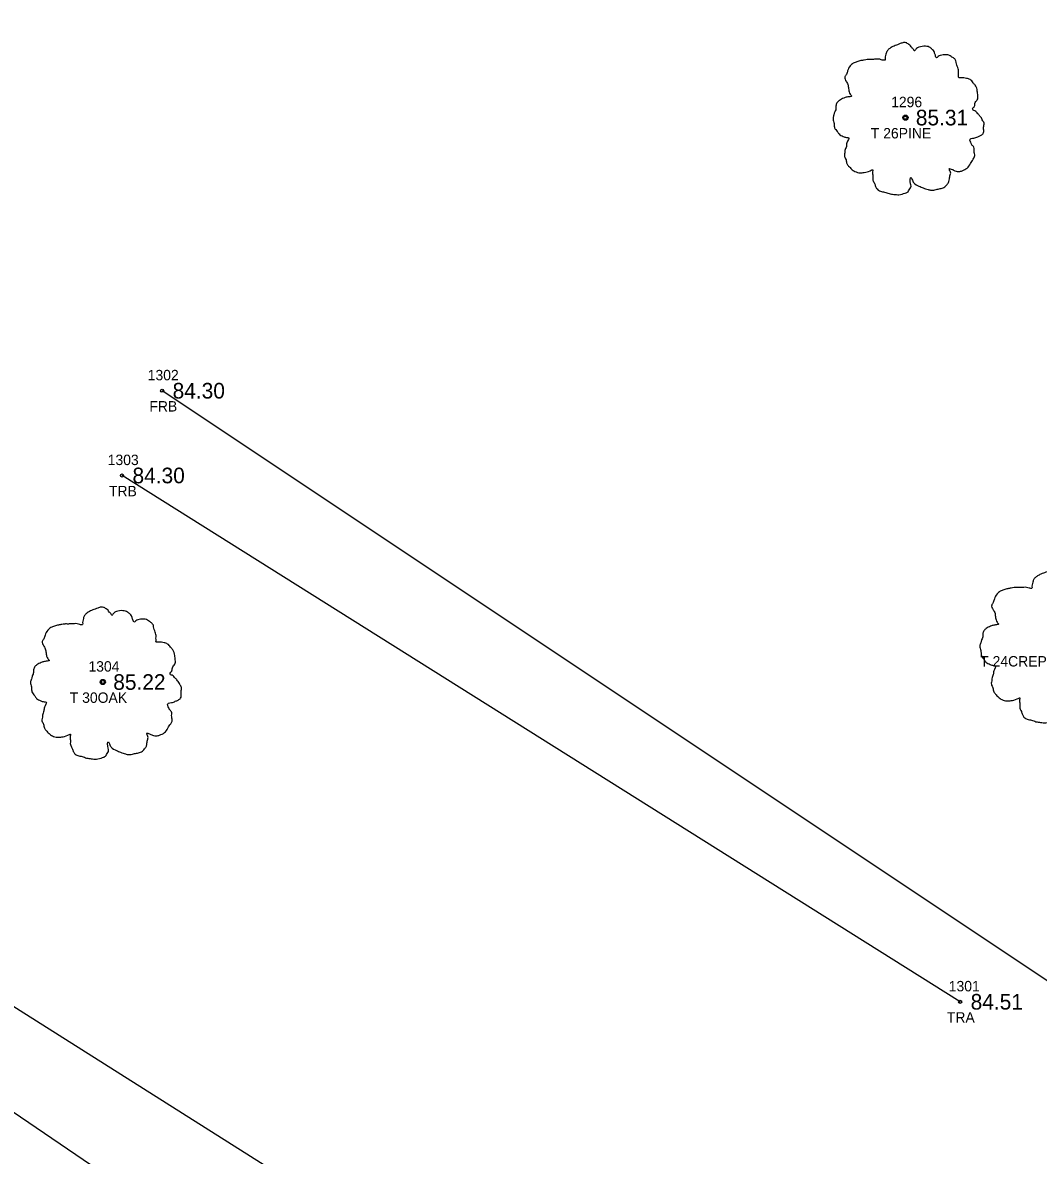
# Model space of a CAD drawing. Extents: x 2139392 to 2143384, y 505395 to 510520.
# Drawn here: x 2141084.9 to 2141182.4, y 509825.4 to 509934.1 of the extents above; entities that cross this region are included whole.
import ezdxf

# ---------------------------------------------------------------- set-up
doc = ezdxf.new("R2010")
doc.units = 0
for name, color, linetype in [('RD_EX_Driveway', 7, 'Continuous'), ('RD_EX_Fence_Other', 7, 'Continuous'), ('RD_EX_Fence_Other_txCode', 7, 'Continuous'), ('RD_EX_TX_Fence_Other_ELEV', 7, 'Continuous'), ('RD_EX_TX_VEG_ELEV', 7, 'Continuous'), ('RD_EX_VEG', 7, 'Continuous'), ('RD_EX_VEG_txCode', 7, 'Continuous'), ('RD_SMD_Locator', 7, 'Continuous')]:
    doc.layers.add(name, color=color, linetype=linetype)

msp = doc.modelspace()

# ---------------------------------------------------------------- linework, layer by layer
at = {"layer": 'RD_EX_Driveway'}
for p, q in [((2141078.27, 509843.32), (2141182.34, 509777.58)), ((2141073.6, 509836.63), (2141177.46, 509766.07))]:
    msp.add_line(p, q, dxfattribs=at)
at = {"layer": 'RD_EX_Fence_Other'}
msp.add_lwpolyline([(2141253.77, 509976.78), (2141199.74, 509831.14), (2141098.33, 509898.78)], dxfattribs=at)
at = {"layer": 'RD_EX_VEG'}
msp.add_line((2141174.93, 509840.11), (2141094.48, 509890.64), dxfattribs=at)
for centre, radius in [((2141169.67, 509925), 0.25), ((2141169.65, 509924.99), 0.0001), ((2141092.63, 509870.81), 0.25), ((2141092.62, 509870.79), 0.0001)]:
    msp.add_circle(centre, radius, dxfattribs=at)
for points in [[(2141169.8, 509932.17), (2141169.5, 509932.2), (2141169.17, 509932.1), (2141168.92, 509932), (2141168.7, 509931.92), (2141168.47, 509931.82), (2141168.17, 509931.65), (2141167.95, 509931.45), (2141167.82, 509931.2), (2141167.77, 509930.97), (2141167.72, 509930.7), (2141167.72, 509930.52), (2141167.6, 509930.5), (2141167.45, 509930.52), (2141167.2, 509930.6), (2141166.95, 509930.6), (2141166.7, 509930.6), (2141166.35, 509930.57), (2141166, 509930.57), (2141165.72, 509930.52), (2141165.4, 509930.47), (2141165.02, 509930.35), (2141164.67, 509930.22), (2141164.37, 509929.97), (2141164.12, 509929.5), (2141164, 509929.15), (2141163.85, 509928.9), (2141164, 509928.45), (2141164.17, 509928.1), (2141164.2, 509927.9), (2141164.27, 509927.47), (2141164.37, 509927.25), (2141164.5, 509927.05), (2141164.42, 509927.02), (2141164.05, 509926.97), (2141163.75, 509926.87), (2141163.33, 509926.65), (2141163.1, 509926.42), (2141163, 509926.1), (2141162.98, 509925.75), (2141162.88, 509925.55), (2141162.8, 509925.28), (2141162.78, 509925.2), (2141162.73, 509924.88), (2141162.83, 509924.43), (2141162.85, 509924.08), (2141162.98, 509923.85), (2141163.13, 509923.68), (2141163.3, 509923.43), (2141163.7, 509923.2), (2141164.02, 509923.1), (2141164.22, 509923.08), (2141164.05, 509922.58), (2141164, 509922.23), (2141163.87, 509921.83), (2141163.87, 509921.75), (2141163.82, 509921.28), (2141163.97, 509920.95), (2141164.05, 509920.58), (2141164.22, 509920.35), (2141164.5, 509920.05), (2141164.82, 509919.83), (2141165.32, 509919.7), (2141165.72, 509919.73), (2141166.3, 509919.9), (2141166.55, 509919.98), (2141166.52, 509919.8), (2141166.55, 509919.43), (2141166.55, 509919), (2141166.7, 509918.68), (2141166.8, 509918.4), (2141166.95, 509918.15), (2141167.27, 509917.93), (2141167.67, 509917.85), (2141168.1, 509917.7), (2141168.55, 509917.63), (2141169.05, 509917.6), (2141169.65, 509917.75), (2141169.92, 509917.88), (2141170.02, 509918.05), (2141170.22, 509918.43), (2141170.17, 509918.65), (2141170.2, 509919.25), (2141170.3, 509919.08), (2141170.47, 509918.73), (2141170.97, 509918.43), (2141171.37, 509918.25), (2141171.85, 509918.1), (2141172.15, 509918.03), (2141172.62, 509918.1), (2141173, 509918.18), (2141173.37, 509918.3), (2141173.67, 509918.58), (2141173.85, 509918.85), (2141173.9, 509919.13), (2141173.97, 509919.5), (2141174.02, 509919.68)], [(2141174.02, 509919.68), (2141173.95, 509919.85), (2141173.9, 509920.1), (2141173.97, 509920.08), (2141174.15, 509920.03), (2141174.42, 509919.9), (2141174.65, 509919.83), (2141174.97, 509919.85), (2141175.24, 509919.95), (2141175.69, 509920.23), (2141175.97, 509920.7), (2141176.24, 509921.1), (2141176.32, 509921.43), (2141176.27, 509921.65), (2141176.24, 509922.15), (2141176.04, 509922.4), (2141175.99, 509922.53), (2141175.89, 509922.93), (2141175.97, 509922.98), (2141176.24, 509923.03), (2141176.62, 509923.15), (2141176.89, 509923.28), (2141177.12, 509923.45), (2141177.19, 509923.68), (2141177.17, 509924.08), (2141177.22, 509924.48), (2141177.14, 509924.63), (2141177.04, 509924.78), (2141176.97, 509924.98), (2141176.82, 509925.13), (2141176.72, 509925.28), (2141176.62, 509925.37), (2141176.49, 509925.52), (2141176.32, 509925.65), (2141176.17, 509925.7), (2141176.12, 509925.85), (2141176.27, 509926.05), (2141176.32, 509926.15), (2141176.34, 509926.37), (2141176.57, 509926.72), (2141176.62, 509927.12), (2141176.57, 509927.55), (2141176.52, 509927.82), (2141176.37, 509928.1), (2141176.17, 509928.35), (2141176.04, 509928.52), (2141175.87, 509928.65), (2141175.54, 509928.77), (2141175.29, 509928.82), (2141174.94, 509928.82), (2141174.75, 509928.87), (2141174.77, 509928.92), (2141174.77, 509929.07), (2141174.77, 509929.35), (2141174.7, 509929.8), (2141174.55, 509930.3), (2141174.55, 509930.32), (2141174.45, 509930.57), (2141174.22, 509930.77), (2141174.05, 509930.87), (2141173.85, 509931), (2141173.6, 509931.02), (2141173.3, 509931.02), (2141173.02, 509930.97), (2141172.82, 509930.87), (2141172.65, 509930.75), (2141172.57, 509930.9), (2141172.47, 509931.2), (2141172.42, 509931.35), (2141172.27, 509931.52), (2141172.05, 509931.72), (2141171.6, 509931.85), (2141170.97, 509931.77), (2141170.67, 509931.57), (2141170.52, 509931.4), (2141170.47, 509931.52), (2141170.27, 509931.72), (2141170.17, 509931.9), (2141170, 509932.02), (2141169.85, 509932.12), (2141169.75, 509932.17)], [(2141183.9, 509881.47), (2141183.6, 509881.5), (2141183.27, 509881.4), (2141183.02, 509881.3), (2141182.8, 509881.22), (2141182.57, 509881.12), (2141182.27, 509880.95), (2141182.05, 509880.75), (2141181.92, 509880.5), (2141181.87, 509880.27), (2141181.82, 509880), (2141181.82, 509879.82), (2141181.7, 509879.8), (2141181.55, 509879.82), (2141181.3, 509879.9), (2141181.05, 509879.9), (2141180.8, 509879.9), (2141180.45, 509879.87), (2141180.1, 509879.87), (2141179.82, 509879.82), (2141179.5, 509879.77), (2141179.12, 509879.65), (2141178.77, 509879.52), (2141178.47, 509879.27), (2141178.22, 509878.8), (2141178.1, 509878.45), (2141177.95, 509878.2), (2141178.1, 509877.75), (2141178.27, 509877.4), (2141178.3, 509877.2), (2141178.37, 509876.77), (2141178.47, 509876.55), (2141178.6, 509876.35), (2141178.52, 509876.32), (2141178.15, 509876.27), (2141177.85, 509876.17), (2141177.42, 509875.95), (2141177.2, 509875.72), (2141177.1, 509875.4), (2141177.07, 509875.05), (2141176.97, 509874.85), (2141176.9, 509874.57), (2141176.87, 509874.5), (2141176.82, 509874.17), (2141176.92, 509873.72), (2141176.95, 509873.37), (2141177.07, 509873.15), (2141177.22, 509872.97), (2141177.4, 509872.72), (2141177.8, 509872.5), (2141178.12, 509872.4), (2141178.32, 509872.37), (2141178.15, 509871.87), (2141178.1, 509871.53), (2141177.97, 509871.13), (2141177.97, 509871.05), (2141177.92, 509870.58), (2141178.07, 509870.25), (2141178.15, 509869.88), (2141178.32, 509869.65), (2141178.6, 509869.35), (2141178.92, 509869.13), (2141179.42, 509869), (2141179.82, 509869.03), (2141180.4, 509869.2), (2141180.65, 509869.28), (2141180.62, 509869.1), (2141180.65, 509868.73), (2141180.65, 509868.3), (2141180.8, 509867.98), (2141180.9, 509867.7), (2141181.05, 509867.45), (2141181.37, 509867.23), (2141181.77, 509867.15), (2141182.2, 509867), (2141182.65, 509866.93), (2141183.15, 509866.9), (2141183.75, 509867.05), (2141184.02, 509867.18), (2141184.12, 509867.35), (2141184.32, 509867.73), (2141184.27, 509867.95), (2141184.3, 509868.55), (2141184.4, 509868.38), (2141184.57, 509868.03), (2141185.07, 509867.73), (2141185.47, 509867.55), (2141185.95, 509867.4), (2141186.25, 509867.33), (2141186.72, 509867.4), (2141187.1, 509867.48), (2141187.47, 509867.6), (2141187.77, 509867.88), (2141187.94, 509868.15), (2141187.99, 509868.43), (2141188.07, 509868.8), (2141188.12, 509868.98)], [(2141092.76, 509877.98), (2141092.46, 509878), (2141092.14, 509877.9), (2141091.89, 509877.81), (2141091.67, 509877.73), (2141091.44, 509877.63), (2141091.14, 509877.46), (2141090.92, 509877.26), (2141090.79, 509877.01), (2141090.74, 509876.78), (2141090.69, 509876.51), (2141090.69, 509876.33), (2141090.57, 509876.31), (2141090.42, 509876.33), (2141090.17, 509876.41), (2141089.92, 509876.41), (2141089.67, 509876.41), (2141089.32, 509876.38), (2141088.97, 509876.38), (2141088.69, 509876.33), (2141088.37, 509876.28), (2141087.99, 509876.16), (2141087.64, 509876.03), (2141087.34, 509875.78), (2141087.09, 509875.31), (2141086.97, 509874.96), (2141086.82, 509874.71), (2141086.97, 509874.26), (2141087.14, 509873.91), (2141087.17, 509873.71), (2141087.24, 509873.28), (2141087.34, 509873.06), (2141087.47, 509872.86), (2141087.39, 509872.83), (2141087.02, 509872.78), (2141086.72, 509872.68), (2141086.29, 509872.46), (2141086.07, 509872.23), (2141085.97, 509871.91), (2141085.94, 509871.56), (2141085.84, 509871.36), (2141085.77, 509871.08), (2141085.74, 509871.01), (2141085.69, 509870.68), (2141085.79, 509870.23), (2141085.82, 509869.88), (2141085.94, 509869.66), (2141086.09, 509869.48), (2141086.27, 509869.23), (2141086.67, 509869.01), (2141086.99, 509868.91), (2141087.19, 509868.88), (2141087.02, 509868.38), (2141086.97, 509868.03), (2141086.84, 509867.63), (2141086.84, 509867.56), (2141086.79, 509867.08), (2141086.94, 509866.76), (2141087.02, 509866.39), (2141087.19, 509866.16), (2141087.47, 509865.86), (2141087.79, 509865.64), (2141088.29, 509865.51), (2141088.69, 509865.54), (2141089.27, 509865.71), (2141089.52, 509865.79), (2141089.49, 509865.61), (2141089.52, 509865.24), (2141089.52, 509864.81), (2141089.67, 509864.49), (2141089.77, 509864.21), (2141089.92, 509863.96), (2141090.24, 509863.74), (2141090.64, 509863.66), (2141091.07, 509863.51), (2141091.52, 509863.44), (2141092.02, 509863.41), (2141092.61, 509863.56), (2141092.89, 509863.69), (2141092.99, 509863.86), (2141093.19, 509864.24), (2141093.14, 509864.46), (2141093.16, 509865.06), (2141093.26, 509864.89), (2141093.44, 509864.54), (2141093.94, 509864.24), (2141094.34, 509864.06), (2141094.81, 509863.91), (2141095.11, 509863.84), (2141095.59, 509863.91), (2141095.96, 509863.99), (2141096.34, 509864.11), (2141096.64, 509864.39), (2141096.81, 509864.66), (2141096.86, 509864.94), (2141096.94, 509865.31), (2141096.99, 509865.49)], [(2141096.99, 509865.49), (2141096.91, 509865.66), (2141096.86, 509865.91), (2141096.94, 509865.89), (2141097.11, 509865.84), (2141097.39, 509865.71), (2141097.61, 509865.64), (2141097.94, 509865.66), (2141098.21, 509865.76), (2141098.66, 509866.04), (2141098.94, 509866.51), (2141099.21, 509866.91), (2141099.29, 509867.23), (2141099.24, 509867.46), (2141099.21, 509867.96), (2141099.01, 509868.21), (2141098.96, 509868.33), (2141098.86, 509868.73), (2141098.94, 509868.78), (2141099.21, 509868.83), (2141099.59, 509868.96), (2141099.86, 509869.08), (2141100.09, 509869.26), (2141100.16, 509869.48), (2141100.14, 509869.88), (2141100.19, 509870.28), (2141100.11, 509870.43), (2141100.01, 509870.58), (2141099.94, 509870.78), (2141099.79, 509870.93), (2141099.69, 509871.08), (2141099.59, 509871.18), (2141099.46, 509871.33), (2141099.29, 509871.46), (2141099.14, 509871.51), (2141099.09, 509871.66), (2141099.24, 509871.86), (2141099.29, 509871.96), (2141099.31, 509872.18), (2141099.54, 509872.53), (2141099.59, 509872.93), (2141099.54, 509873.36), (2141099.49, 509873.63), (2141099.34, 509873.91), (2141099.14, 509874.16), (2141099.01, 509874.33), (2141098.84, 509874.46), (2141098.51, 509874.58), (2141098.26, 509874.63), (2141097.91, 509874.63), (2141097.71, 509874.68), (2141097.74, 509874.73), (2141097.74, 509874.88), (2141097.74, 509875.16), (2141097.66, 509875.61), (2141097.51, 509876.11), (2141097.51, 509876.13), (2141097.41, 509876.38), (2141097.19, 509876.58), (2141097.01, 509876.68), (2141096.81, 509876.81), (2141096.56, 509876.83), (2141096.26, 509876.83), (2141095.99, 509876.78), (2141095.79, 509876.68), (2141095.61, 509876.56), (2141095.54, 509876.71), (2141095.44, 509877.01), (2141095.39, 509877.16), (2141095.24, 509877.33), (2141095.01, 509877.53), (2141094.56, 509877.66), (2141093.94, 509877.58), (2141093.64, 509877.38), (2141093.49, 509877.21), (2141093.44, 509877.33), (2141093.24, 509877.53), (2141093.14, 509877.71), (2141092.96, 509877.83), (2141092.81, 509877.93), (2141092.71, 509877.98)]]:
    msp.add_spline(points, degree=3, dxfattribs=at)
at = {"layer": 'RD_SMD_Locator'}
for centre in [(2141169.67, 509925), (2141098.33, 509898.78), (2141094.48, 509890.64), (2141092.63, 509870.81), (2141174.93, 509840.11)]:
    msp.add_circle(centre, 0.15, dxfattribs=at)

# ---------------------------------------------------------------- texts
at = {"layer": 'RD_EX_Fence_Other_txCode'}
for s, p in [('1302', (2141096.94, 509899.78)), ('FRB', (2141097.1, 509896.78))]:
    msp.add_text(s, height=1, dxfattribs=at).set_placement(p)
at = {"layer": 'RD_EX_TX_Fence_Other_ELEV'}
msp.add_text('84.30', height=1.5, dxfattribs=at).set_placement((2141099.33, 509898.03))
at = {"layer": 'RD_EX_TX_VEG_ELEV'}
for s, p in [('85.31', (2141170.67, 509924.25)), ('84.30', (2141095.48, 509889.89)), ('85.22', (2141093.63, 509870.06)), ('84.51', (2141175.93, 509839.36))]:
    msp.add_text(s, height=1.5, dxfattribs=at).set_placement(p)
at = {"layer": 'RD_EX_VEG_txCode'}
for s, p in [('1296', (2141168.3, 509926)), ('T 26PINE', (2141166.35, 509923)), ('1303', (2141093.1, 509891.64)), ('TRB', (2141093.22, 509888.64)), ('1304', (2141091.25, 509871.81)), ('T 24CREPEMYRTLE', (2141176.85, 509872.3)), ('T 30OAK', (2141089.46, 509868.81)), ('1301', (2141173.83, 509841.11)), ('TRA', (2141173.65, 509838.11))]:
    msp.add_text(s, height=1, dxfattribs=at).set_placement(p)

doc.saveas('drawing.dxf')
